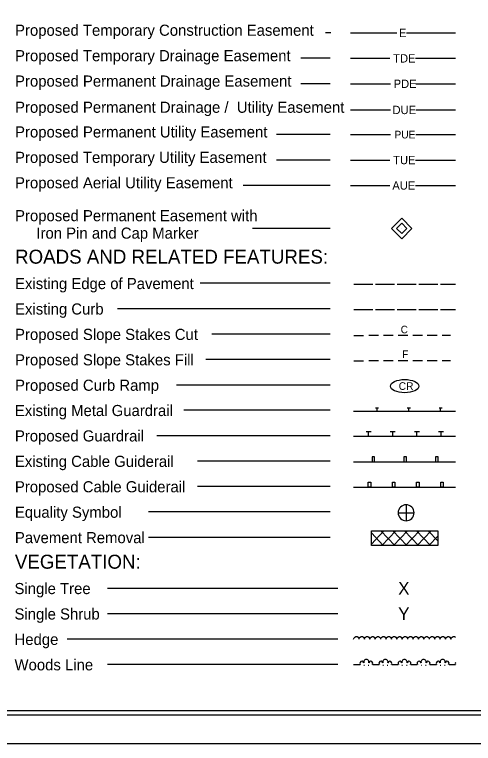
# Model space of a CAD drawing. Extents: x 573687 to 575553, y -54556 to -52223.
# Drawn here: x 574249 to 574609, y -54556 to -53982 of the extents above; entities that cross this region are included whole.
import ezdxf

# ---------------------------------------------------------------- set-up
doc = ezdxf.new("R2010")
doc.units = 0
for name, color, linetype in [('Prop Easement Permanent Drainage Utility', 7, 'Continuous'), ('Prop ROW Permanent Easement CELL', 7, 'Continuous'), ('Prop WCC CELL', 7, 'Continuous'), ('Sheet Cutting Line CELL', 7, 'Continuous'), ('Sheet Plot Border Inside CELL', 7, 'Continuous'), ('Sheet Plot Border Outside CELL', 7, 'Continuous'), ('Sheet Symbology CELL', 7, 'Continuous')]:
    doc.layers.add(name, color=color, linetype=linetype)

msp = doc.modelspace()

# ---------------------------------------------------------------- linework, layer by layer
at = {"layer": 'Prop Easement Permanent Drainage Utility'}
for p, q in [((574512.94, -54057.15), (574544.24, -54057.15)), ((574564.24, -54057.15), (574595.44, -54057.15))]:
    msp.add_line(p, q, dxfattribs=at)
at = {"layer": 'Prop ROW Permanent Easement CELL'}
msp.add_line((574553.09, -54150.4), (574553.09, -54150.4), dxfattribs=at)
for points in [[(574553.09, -54142.35), (574561.14, -54150.4), (574553.09, -54158.45), (574545.04, -54150.4)], [(574553.09, -54146.37), (574557.12, -54150.4), (574553.09, -54154.43), (574549.06, -54150.4)]]:
    msp.add_lwpolyline(points, close=True, dxfattribs=at)
at = {"layer": 'Prop WCC CELL'}
msp.add_ellipse((574555.41, -54274.42), major_axis=(11.21, 0), ratio=0.462467, dxfattribs=at)
at = {"layer": 'Sheet Cutting Line CELL'}
msp.add_line((573687.45, -54555.5), (575371.45, -54555.5), dxfattribs=at)
at = {"layer": 'Sheet Plot Border Inside CELL'}
msp.add_lwpolyline([(573700.45, -54533.05), (575366.95, -54533.05), (575366.95, -53477.95), (573700.45, -53477.95)], close=True, dxfattribs=at)
at = {"layer": 'Sheet Plot Border Outside CELL'}
msp.add_lwpolyline([(573687.45, -54555.5), (575371.45, -54555.5), (575371.45, -53455.5), (573687.45, -53455.5)], close=True, dxfattribs=at)
at = {"layer": 'Sheet Symbology CELL'}
for p, q in [((574497.3, -53996.57), (574493.12, -53996.57)), ((574512.94, -53996.57), (574515.56, -53996.57)), ((574515.56, -53996.57), (574549.31, -53996.57)), ((574556.81, -53996.57), (574590.56, -53996.57)), ((574590.56, -53996.57), (574595.44, -53996.57)), ((574496.91, -54016.57), (574473.76, -54016.57)), ((574512.94, -54016.57), (574516.29, -54016.57)), ((574516.29, -54016.57), (574543.79, -54016.57)), ((574563.79, -54016.57), (574591.29, -54016.57)), ((574591.29, -54016.57), (574595.44, -54016.57)), ((574496.91, -54036.57), (574473.76, -54036.57)), ((574512.94, -54036.57), (574516.74, -54036.57)), ((574516.74, -54036.57), (574544.24, -54036.57)), ((574564.24, -54036.57), (574591.74, -54036.57)), ((574591.74, -54036.57), (574595.44, -54036.57)), ((574496.91, -54076.58), (574454.78, -54076.58)), ((574512.94, -54076.58), (574516.78, -54076.58)), ((574516.78, -54076.58), (574544.28, -54076.58)), ((574564.28, -54076.58), (574591.78, -54076.58)), ((574591.78, -54076.58), (574595.44, -54076.58)), ((574496.91, -54096.58), (574454.78, -54096.58)), ((574512.94, -54096.58), (574516.29, -54096.58)), ((574516.29, -54096.58), (574543.79, -54096.58)), ((574563.79, -54096.58), (574591.29, -54096.58)), ((574591.29, -54096.58), (574595.44, -54096.58)), ((574496.91, -54116.58), (574428.46, -54116.58)), ((574512.94, -54116.58), (574516.29, -54116.58)), ((574516.29, -54116.58), (574543.79, -54116.58)), ((574563.79, -54116.58), (574591.29, -54116.58)), ((574591.29, -54116.58), (574595.44, -54116.58)), ((574496.91, -54150.4), (574435.9, -54150.4)), ((574496.91, -54193.56), (574394.56, -54193.56)), ((574515.44, -54194.13), (574530.44, -54194.13)), ((574532.44, -54194.13), (574547.44, -54194.13)), ((574549.44, -54194.13), (574564.44, -54194.13)), ((574566.44, -54194.13), (574581.44, -54194.13)), ((574583.44, -54194.13), (574595.44, -54194.13)), ((574496.91, -54213.56), (574329.76, -54213.56)), ((574515.44, -54214.13), (574530.44, -54214.13)), ((574532.44, -54214.13), (574547.44, -54214.13)), ((574549.44, -54214.13), (574564.44, -54214.13)), ((574566.44, -54214.13), (574581.44, -54214.13)), ((574583.44, -54214.13), (574595.44, -54214.13)), ((574496.91, -54233.56), (574403.73, -54233.56)), ((574515.44, -54234.61), (574523.04, -54234.61)), ((574534.74, -54234.61), (574527.19, -54234.61)), ((574546.24, -54234.61), (574538.64, -54234.61)), ((574557.99, -54234.61), (574550.19, -54234.61)), ((574569.44, -54234.61), (574561.69, -54234.61)), ((574580.99, -54234.61), (574573.14, -54234.61)), ((574591.29, -54234.61), (574584.89, -54234.61)), ((574496.91, -54253.56), (574399.18, -54253.56)), ((574515.44, -54254.61), (574523.04, -54254.61)), ((574534.74, -54254.61), (574527.19, -54254.61)), ((574546.24, -54254.61), (574538.64, -54254.61)), ((574557.99, -54254.61), (574550.19, -54254.61)), ((574569.44, -54254.61), (574561.69, -54254.61)), ((574580.99, -54254.61), (574573.14, -54254.61)), ((574591.29, -54254.61), (574584.89, -54254.61)), ((574496.91, -54273.56), (574375.99, -54273.56)), ((574496.76, -54293.44), (574381.92, -54293.44)), ((574515.29, -54294.01), (574595.29, -54294.01)), ((574532.43, -54291.51), (574534.93, -54291.51)), ((574533.68, -54294.01), (574533.68, -54291.51)), ((574557.43, -54291.51), (574559.93, -54291.51)), ((574558.68, -54294.01), (574558.68, -54291.51)), ((574582.43, -54291.51), (574584.93, -54291.51)), ((574583.68, -54294.01), (574583.68, -54291.51)), ((574525.01, -54310.06), (574529.01, -54310.06)), ((574527.01, -54314.01), (574527.01, -54310.06)), ((574544.01, -54310.06), (574548.01, -54310.06)), ((574546.01, -54314.01), (574546.01, -54310.06)), ((574563.01, -54310.06), (574567.01, -54310.06)), ((574565.01, -54314.01), (574565.01, -54310.06)), ((574582.01, -54310.06), (574586.01, -54310.06)), ((574584.01, -54314.01), (574584.01, -54310.06)), ((574496.76, -54313.44), (574360.52, -54313.44)), ((574595.29, -54314.01), (574515.29, -54314.01)), ((574496.76, -54333.44), (574392.46, -54333.44)), ((574515.29, -54334.01), (574595.29, -54334.01)), ((574496.76, -54353.44), (574392.46, -54353.44)), ((574515.29, -54354.01), (574595.29, -54354.01)), ((574556.51, -54367.77), (574556.51, -54374.02)), ((574496.76, -54373.44), (574354.13, -54373.44)), ((574550.26, -54374.02), (574556.51, -54374.02)), ((574556.51, -54374.02), (574556.51, -54380.27)), ((574556.51, -54374.02), (574562.76, -54374.02)), ((574529.24, -54388.15), (574581.34, -54388.15)), ((574529.24, -54399.85), (574529.24, -54388.15)), ((574529.24, -54388.75), (574529.79, -54388.15)), ((574529.24, -54398.7), (574539.09, -54388.15)), ((574538.49, -54399.85), (574529.24, -54389.95)), ((574547.79, -54399.85), (574536.79, -54388.15)), ((574537.39, -54399.85), (574548.39, -54388.15)), ((574557.04, -54399.85), (574546.09, -54388.15)), ((574546.64, -54399.85), (574557.69, -54388.15)), ((574566.34, -54399.85), (574555.34, -54388.15)), ((574555.94, -54399.85), (574566.94, -54388.15)), ((574575.64, -54399.85), (574564.59, -54388.15)), ((574565.24, -54399.85), (574576.19, -54388.15)), ((574581.34, -54396.1), (574573.89, -54388.15)), ((574574.49, -54399.85), (574581.34, -54392.55)), ((574581.34, -54388.15), (574581.34, -54399.85)), ((574496.76, -54393.44), (574354.13, -54393.44)), ((574581.34, -54399.85), (574529.24, -54399.85)), ((574502.9, -54433.51), (574321.77, -54433.51)), ((574502.9, -54453.51), (574321.77, -54453.51)), ((574502.9, -54473.51), (574290.21, -54473.51)), ((574515.29, -54473.51), (574515.59, -54472.56)), ((574515.59, -54472.56), (574516.19, -54471.91)), ((574516.19, -54471.91), (574516.99, -54471.46)), ((574516.99, -54471.46), (574517.94, -54471.46)), ((574517.94, -54471.46), (574518.74, -54471.96)), ((574518.74, -54471.96), (574519.29, -54472.61)), ((574519.29, -54472.61), (574519.49, -54473.46)), ((574519.54, -54473.51), (574519.84, -54472.56)), ((574519.84, -54472.56), (574520.44, -54471.91)), ((574520.44, -54471.91), (574521.24, -54471.46)), ((574521.24, -54471.46), (574522.19, -54471.46)), ((574522.19, -54471.46), (574522.99, -54471.96)), ((574522.99, -54471.96), (574523.54, -54472.61)), ((574523.54, -54472.61), (574523.74, -54473.46)), ((574523.79, -54473.51), (574524.09, -54472.56)), ((574524.09, -54472.56), (574524.69, -54471.91)), ((574524.69, -54471.91), (574525.49, -54471.46)), ((574525.49, -54471.46), (574526.44, -54471.46)), ((574526.44, -54471.46), (574527.24, -54471.96)), ((574527.24, -54471.96), (574527.79, -54472.61)), ((574527.79, -54472.61), (574527.99, -54473.46)), ((574528.04, -54473.51), (574528.34, -54472.56)), ((574528.34, -54472.56), (574528.94, -54471.91)), ((574528.94, -54471.91), (574529.74, -54471.46)), ((574529.74, -54471.46), (574530.69, -54471.46)), ((574530.69, -54471.46), (574531.49, -54471.96)), ((574531.49, -54471.96), (574532.04, -54472.61)), ((574532.04, -54472.61), (574532.24, -54473.46)), ((574532.29, -54473.51), (574532.59, -54472.56)), ((574532.59, -54472.56), (574533.19, -54471.91)), ((574533.19, -54471.91), (574533.99, -54471.46)), ((574533.99, -54471.46), (574534.94, -54471.46)), ((574534.94, -54471.46), (574535.74, -54471.96)), ((574535.74, -54471.96), (574536.29, -54472.61)), ((574536.29, -54472.61), (574536.49, -54473.46)), ((574536.54, -54473.51), (574536.84, -54472.56)), ((574536.84, -54472.56), (574537.44, -54471.91)), ((574537.44, -54471.91), (574538.24, -54471.46)), ((574538.24, -54471.46), (574539.19, -54471.46)), ((574539.19, -54471.46), (574539.99, -54471.96)), ((574539.99, -54471.96), (574540.54, -54472.61)), ((574540.54, -54472.61), (574540.74, -54473.46)), ((574540.79, -54473.51), (574541.09, -54472.56)), ((574541.09, -54472.56), (574541.69, -54471.91)), ((574541.69, -54471.91), (574542.49, -54471.46)), ((574542.49, -54471.46), (574543.44, -54471.46)), ((574543.44, -54471.46), (574544.24, -54471.96)), ((574544.24, -54471.96), (574544.79, -54472.61)), ((574544.79, -54472.61), (574544.99, -54473.46)), ((574545.04, -54473.51), (574545.34, -54472.56)), ((574545.34, -54472.56), (574545.94, -54471.91)), ((574545.94, -54471.91), (574546.74, -54471.46)), ((574546.74, -54471.46), (574547.69, -54471.46)), ((574547.69, -54471.46), (574548.49, -54471.96)), ((574548.49, -54471.96), (574549.04, -54472.61)), ((574549.04, -54472.61), (574549.24, -54473.46)), ((574549.29, -54473.51), (574549.59, -54472.56)), ((574549.59, -54472.56), (574550.19, -54471.91)), ((574550.19, -54471.91), (574550.99, -54471.46)), ((574550.99, -54471.46), (574551.94, -54471.46)), ((574551.94, -54471.46), (574552.74, -54471.96)), ((574552.74, -54471.96), (574553.29, -54472.61)), ((574553.29, -54472.61), (574553.49, -54473.46)), ((574553.54, -54473.51), (574553.84, -54472.56)), ((574553.84, -54472.56), (574554.44, -54471.91)), ((574554.44, -54471.91), (574555.24, -54471.46)), ((574555.24, -54471.46), (574556.19, -54471.46)), ((574556.19, -54471.46), (574556.99, -54471.96)), ((574556.99, -54471.96), (574557.54, -54472.61)), ((574557.54, -54472.61), (574557.74, -54473.46)), ((574557.79, -54473.51), (574558.09, -54472.56)), ((574558.09, -54472.56), (574558.69, -54471.91)), ((574558.69, -54471.91), (574559.49, -54471.46)), ((574559.49, -54471.46), (574560.44, -54471.46)), ((574560.44, -54471.46), (574561.24, -54471.96)), ((574561.24, -54471.96), (574561.79, -54472.61)), ((574561.79, -54472.61), (574561.99, -54473.46)), ((574562.04, -54473.51), (574562.34, -54472.56)), ((574562.34, -54472.56), (574562.94, -54471.91)), ((574562.94, -54471.91), (574563.74, -54471.46)), ((574563.74, -54471.46), (574564.69, -54471.46)), ((574564.69, -54471.46), (574565.49, -54471.96)), ((574565.49, -54471.96), (574566.04, -54472.61)), ((574566.04, -54472.61), (574566.24, -54473.46)), ((574566.29, -54473.51), (574566.59, -54472.56)), ((574566.59, -54472.56), (574567.19, -54471.91)), ((574567.19, -54471.91), (574567.99, -54471.46)), ((574567.99, -54471.46), (574568.94, -54471.46)), ((574568.94, -54471.46), (574569.74, -54471.96)), ((574569.74, -54471.96), (574570.29, -54472.61)), ((574570.29, -54472.61), (574570.49, -54473.46)), ((574570.54, -54473.51), (574570.84, -54472.56)), ((574570.84, -54472.56), (574571.44, -54471.91)), ((574571.44, -54471.91), (574572.24, -54471.46)), ((574572.24, -54471.46), (574573.19, -54471.46)), ((574573.19, -54471.46), (574573.99, -54471.96)), ((574573.99, -54471.96), (574574.54, -54472.61)), ((574574.54, -54472.61), (574574.74, -54473.46)), ((574574.79, -54473.51), (574575.09, -54472.56)), ((574575.09, -54472.56), (574575.69, -54471.91)), ((574575.69, -54471.91), (574576.49, -54471.46)), ((574576.49, -54471.46), (574577.44, -54471.46)), ((574577.44, -54471.46), (574578.24, -54471.96)), ((574578.24, -54471.96), (574578.79, -54472.61)), ((574578.79, -54472.61), (574578.99, -54473.46)), ((574579.04, -54473.51), (574579.34, -54472.56)), ((574579.34, -54472.56), (574579.94, -54471.91)), ((574579.94, -54471.91), (574580.74, -54471.46)), ((574580.74, -54471.46), (574581.69, -54471.46)), ((574581.69, -54471.46), (574582.49, -54471.96)), ((574582.49, -54471.96), (574583.04, -54472.61)), ((574583.04, -54472.61), (574583.24, -54473.46)), ((574583.29, -54473.51), (574583.59, -54472.56)), ((574583.59, -54472.56), (574584.19, -54471.91)), ((574584.19, -54471.91), (574584.99, -54471.46)), ((574584.99, -54471.46), (574585.94, -54471.46)), ((574585.94, -54471.46), (574586.74, -54471.96)), ((574586.74, -54471.96), (574587.29, -54472.61)), ((574587.29, -54472.61), (574587.49, -54473.46)), ((574587.54, -54473.51), (574587.84, -54472.56)), ((574587.84, -54472.56), (574588.44, -54471.91)), ((574588.44, -54471.91), (574589.24, -54471.46)), ((574589.24, -54471.46), (574590.19, -54471.46)), ((574590.19, -54471.46), (574590.99, -54471.96)), ((574590.99, -54471.96), (574591.54, -54472.61)), ((574591.54, -54472.61), (574591.74, -54473.46)), ((574591.79, -54473.51), (574592.09, -54472.56)), ((574592.09, -54472.56), (574592.69, -54471.91)), ((574592.69, -54471.91), (574593.49, -54471.46)), ((574593.49, -54471.46), (574594.44, -54471.46)), ((574594.44, -54471.46), (574595.24, -54471.96)), ((574595.24, -54471.96), (574595.29, -54472.01)), ((574502.9, -54493.51), (574321.77, -54493.51)), ((574515.29, -54493.51), (574520.29, -54493.51)), ((574523.24, -54494.01), (574523.74, -54494.01)), ((574526.74, -54494.01), (574527.24, -54494.01)), ((574530.29, -54493.51), (574535.29, -54493.51)), ((574538.24, -54494.01), (574538.74, -54494.01)), ((574541.74, -54494.01), (574542.24, -54494.01)), ((574545.29, -54493.51), (574550.29, -54493.51)), ((574553.24, -54494.01), (574553.74, -54494.01)), ((574556.74, -54494.01), (574557.24, -54494.01)), ((574560.29, -54493.51), (574565.29, -54493.51)), ((574568.24, -54494.01), (574568.74, -54494.01)), ((574571.74, -54494.01), (574572.24, -54494.01)), ((574575.29, -54493.51), (574580.29, -54493.51)), ((574583.24, -54494.01), (574583.74, -54494.01)), ((574586.74, -54494.01), (574587.24, -54494.01)), ((574590.29, -54493.51), (574595.29, -54493.51))]:
    msp.add_line(p, q, dxfattribs=at)
for points in [[(575354.45, -53480.5), (573854.45, -53480.5), (573854.45, -54529.49), (575354.45, -54529.49)], [(574529.76, -54334.01), (574531.76, -54334.01), (574531.76, -54330.01), (574529.76, -54330.01)], [(574554.76, -54334.01), (574556.76, -54334.01), (574556.76, -54330.01), (574554.76, -54330.01)], [(574579.76, -54334.01), (574581.76, -54334.01), (574581.76, -54330.01), (574579.76, -54330.01)], [(574526.75, -54350.01), (574528.75, -54350.01), (574528.75, -54354.01), (574526.75, -54354.01)], [(574545.75, -54350.01), (574547.75, -54350.01), (574547.75, -54354.01), (574545.75, -54354.01)], [(574564.75, -54350.01), (574566.75, -54350.01), (574566.75, -54354.01), (574564.75, -54354.01)], [(574583.75, -54350.01), (574585.75, -54350.01), (574585.75, -54354.01), (574583.75, -54354.01)]]:
    msp.add_lwpolyline(points, close=True, dxfattribs=at)
for centre, radius, start, end in [((574556.51, -54374.03), 6.25, 89.99439, 179.99893), ((574556.51, -54374.03), 6.25, 359.99439, 89.99893), ((574556.51, -54374.03), 6.25, 179.99439, 269.99892), ((574556.51, -54374.03), 6.25, 269.99439, 359.99893), ((574525.24, -54491.49), 2.06, 345.96376, 194.03624), ((574540.24, -54491.49), 2.06, 345.96376, 194.03624), ((574555.24, -54491.49), 2.06, 345.96376, 194.03624), ((574570.24, -54491.49), 2.06, 345.96376, 194.03624), ((574585.24, -54491.49), 2.06, 345.96376, 194.03624), ((574521.74, -54492.49), 1.58, 18.43495, 219.23152), ((574528.74, -54492.49), 1.58, 320.76848, 161.56505), ((574536.74, -54492.49), 1.58, 18.43495, 219.23152), ((574543.74, -54492.49), 1.58, 320.76848, 161.56505), ((574551.74, -54492.49), 1.58, 18.43495, 219.23152), ((574558.74, -54492.49), 1.58, 320.76848, 161.56505), ((574566.74, -54492.49), 1.58, 18.43495, 219.23152), ((574573.74, -54492.49), 1.58, 320.76848, 161.56505), ((574581.74, -54492.49), 1.58, 18.43495, 219.23152), ((574588.74, -54492.49), 1.58, 320.76848, 161.56505), ((574596.74, -54492.49), 1.58, 156.25102, 203.74899)]:
    msp.add_arc(centre, radius, start, end, dxfattribs=at)

# ---------------------------------------------------------------- texts
at = {"layer": 'Prop Easement Permanent Drainage Utility'}
msp.add_text('DUE', height=6.55, dxfattribs=at).set_placement((574545.84, -54060.45))
at = {"layer": 'Prop WCC CELL'}
msp.add_text('CR', height=6, dxfattribs=at).set_placement((574550.7, -54277.38))
at = {"layer": 'Sheet Symbology CELL'}
for s, height, p in [('Proposed Temporary Construction Easement', 8.75, (574249.16, -53998.83)), ('E', 6.55, (574550.91, -53999.87)), ('Proposed Temporary Drainage Easement', 8.75, (574249.16, -54018.83)), ('TDE', 6.55, (574546.39, -54019.87)), ('Proposed Permanent Drainage Easement', 8.75, (574249.16, -54038.83)), ('PDE', 6.55, (574546.74, -54039.87)), ('Proposed Permanent Drainage /  Utility Easement', 8.75, (574249.16, -54059.41)), ('Proposed Permanent Utility Easement', 8.75, (574249.16, -54078.84)), ('PUE', 6, (574547.38, -54079.58)), ('Proposed Temporary Utility Easement', 8.75, (574249.16, -54098.84)), ('TUE', 6.55, (574546.37, -54099.88)), ('Proposed Aerial Utility Easement', 8.75, (574249.16, -54118.84)), ('AUE', 6.55, (574545.72, -54119.88)), ('Proposed Permanent Easement with', 8.75, (574249.16, -54144.7)), ('Iron Pin and Cap Marker', 8.75, (574265.93, -54158.45)), ('ROADS AND RELATED FEATURES:', 11, (574249.16, -54178.11)), ('Existing Edge of Pavement', 8.75, (574249.16, -54198.11)), ('Existing Curb', 8.75, (574249.16, -54218.11)), ('C', 5.93, (574552.24, -54232.87)), ('Proposed Slope Stakes Cut', 8.75, (574249.16, -54238.11)), ('Proposed Slope Stakes Fill', 8.75, (574249.16, -54258.11)), ('F', 5.93, (574553.44, -54252.24)), ('Proposed Curb Ramp', 8.75, (574249.16, -54278.11)), ('Existing Metal Guardrail', 8.75, (574249.01, -54297.99)), ('Proposed Guardrail', 8.75, (574249.02, -54317.97)), ('Existing Cable Guiderail', 8.75, (574249.02, -54337.97)), ('Proposed Cable Guiderail', 8.75, (574249.02, -54357.97)), ('Equality Symbol', 8.75, (574249.02, -54377.97)), ('Pavement Removal', 8.75, (574249.02, -54397.97)), ('VEGETATION:', 11, (574249.01, -54418.06)), ('Single Tree', 8.75, (574248.73, -54438.03)), ('X', 10, (574550.29, -54438.51)), ('Single Shrub', 8.75, (574248.73, -54458.03)), ('Y', 10, (574550.29, -54458.51)), ('Hedge', 8.75, (574248.73, -54478.03)), ('Woods Line', 8.75, (574248.73, -54498.03))]:
    msp.add_text(s, height=height, dxfattribs=at).set_placement(p)

doc.saveas('drawing.dxf')
